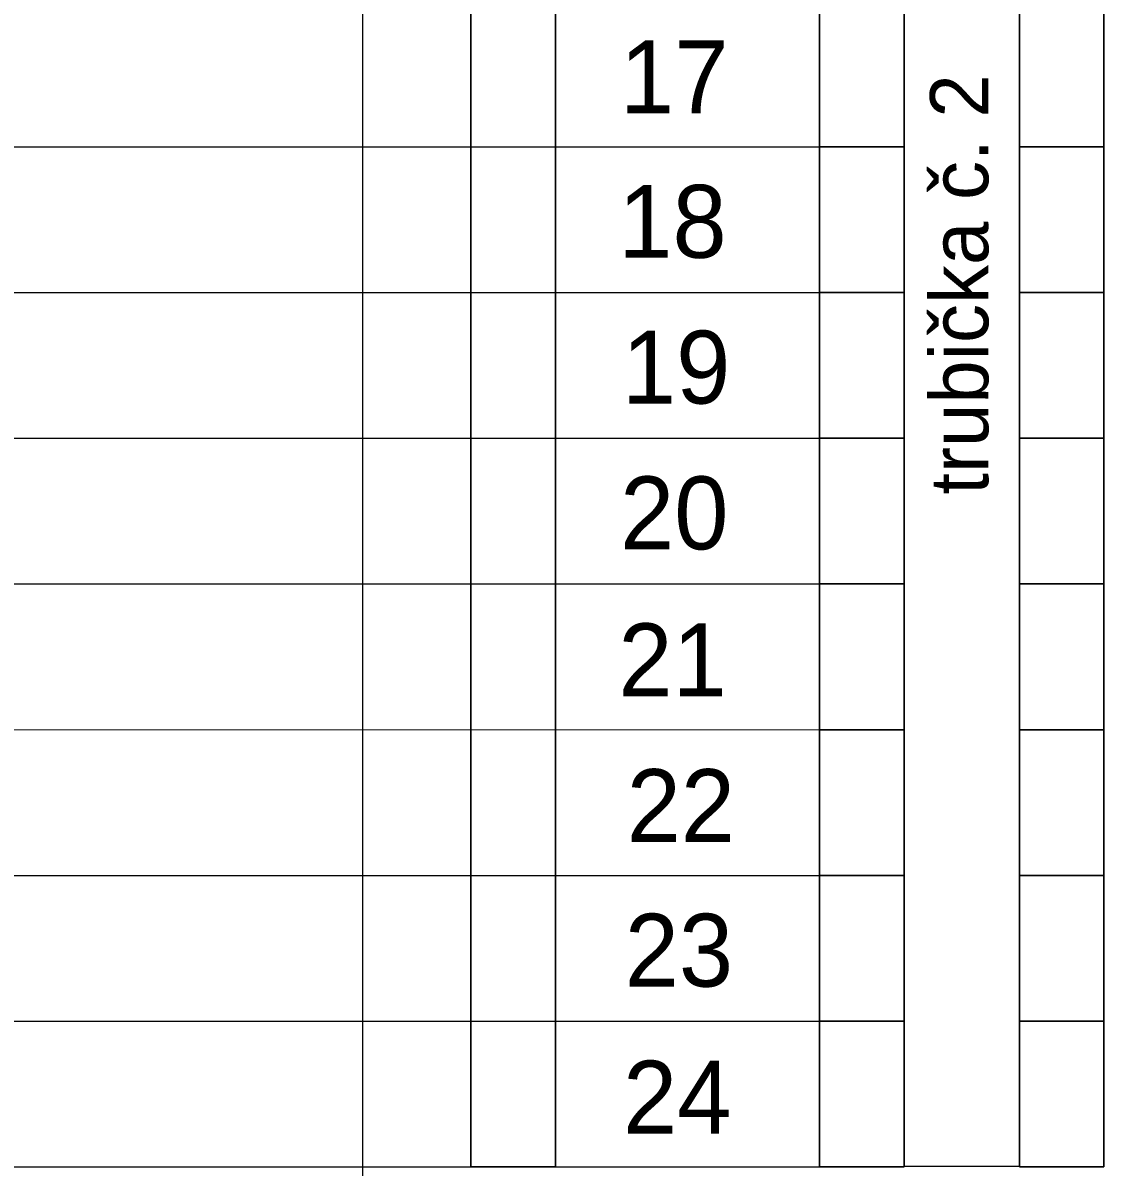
# Model space of a CAD drawing. Extents: x 1901 to 2519, y -3585 to -3154.
# Drawn here: x 2006.66 to 2032.79, y -3287.48 to -3259.84 of the extents above; entities that cross this region are included whole.
import ezdxf

# ---------------------------------------------------------------- set-up
doc = ezdxf.new("R2010")
doc.units = 0
doc.layers.add('rozvláknění', color=7, linetype='Continuous')

msp = doc.modelspace()

# ---------------------------------------------------------------- linework, layer by layer
at = {"layer": 'rozvláknění'}
for p, q in [((1933.193, -3262.837), (2025.898, -3262.839)), ((1933.193, -3266.355), (2025.898, -3266.357)), ((1933.193, -3269.874), (2025.898, -3269.876)), ((1933.193, -3273.392), (2025.898, -3273.394)), ((1933.193, -3276.91), (2025.898, -3276.912)), ((1933.193, -3280.428), (2025.898, -3280.43)), ((1933.193, -3283.946), (2025.898, -3283.948)), ((1933.193, -3287.465), (2025.898, -3287.467))]:
    msp.add_line(p, q, dxfattribs=at)
for points in [[(2014.869, -3178.545), (2059.522, -3178.544), (2059.522, -3570.656), (2014.869, -3570.656)], [(2019.518, -3287.467), (2017.476, -3287.467), (2017.476, -3245.248), (2019.518, -3245.248)], [(2027.939, -3245.248), (2030.726, -3245.248), (2030.726, -3287.463), (2027.939, -3287.463)], [(2025.898, -3259.321), (2027.939, -3259.321), (2027.939, -3262.839), (2025.898, -3262.839)], [(2030.726, -3259.321), (2032.767, -3259.321), (2032.767, -3262.839), (2030.726, -3262.839)], [(2030.726, -3259.321), (2032.767, -3259.321), (2032.767, -3262.839), (2030.726, -3262.839)], [(2025.898, -3262.839), (2027.939, -3262.839), (2027.939, -3266.357), (2025.898, -3266.357)], [(2030.726, -3262.839), (2032.767, -3262.839), (2032.767, -3266.357), (2030.726, -3266.357)], [(2030.726, -3262.839), (2032.767, -3262.839), (2032.767, -3266.357), (2030.726, -3266.357)], [(2025.898, -3266.357), (2027.939, -3266.357), (2027.939, -3269.876), (2025.898, -3269.876)], [(2030.726, -3266.357), (2032.767, -3266.357), (2032.767, -3269.876), (2030.726, -3269.876)], [(2030.726, -3266.357), (2032.767, -3266.357), (2032.767, -3269.876), (2030.726, -3269.876)], [(2025.898, -3269.876), (2027.939, -3269.876), (2027.939, -3273.394), (2025.898, -3273.394)], [(2030.726, -3269.876), (2032.767, -3269.876), (2032.767, -3273.394), (2030.726, -3273.394)], [(2030.726, -3269.876), (2032.767, -3269.876), (2032.767, -3273.394), (2030.726, -3273.394)], [(2025.898, -3273.394), (2027.939, -3273.394), (2027.939, -3276.912), (2025.898, -3276.912)], [(2030.726, -3273.394), (2032.767, -3273.394), (2032.767, -3276.912), (2030.726, -3276.912)], [(2030.726, -3273.394), (2032.767, -3273.394), (2032.767, -3276.912), (2030.726, -3276.912)], [(2025.898, -3276.912), (2027.939, -3276.912), (2027.939, -3280.43), (2025.898, -3280.43)], [(2030.726, -3276.912), (2032.767, -3276.912), (2032.767, -3280.43), (2030.726, -3280.43)], [(2030.726, -3276.912), (2032.767, -3276.912), (2032.767, -3280.43), (2030.726, -3280.43)], [(2025.898, -3280.43), (2027.939, -3280.43), (2027.939, -3283.948), (2025.898, -3283.948)], [(2030.726, -3280.43), (2032.767, -3280.43), (2032.767, -3283.948), (2030.726, -3283.948)], [(2030.726, -3280.43), (2032.767, -3280.43), (2032.767, -3283.948), (2030.726, -3283.948)], [(2025.898, -3283.948), (2027.939, -3283.948), (2027.939, -3287.467), (2025.898, -3287.467)], [(2030.726, -3283.948), (2032.767, -3283.948), (2032.767, -3287.467), (2030.726, -3287.467)], [(2030.726, -3283.948), (2032.767, -3283.948), (2032.767, -3287.467), (2030.726, -3287.467)]]:
    msp.add_lwpolyline(points, close=True, dxfattribs=at)
for points in [[(2019.518, -3245.248), (2017.476, -3245.248), (2017.476, -3287.467), (2019.518, -3287.467), (2019.518, -3245.248)], [(2019.518, -3245.248), (2017.476, -3245.248), (2017.476, -3287.467), (2019.518, -3287.467), (2019.518, -3245.248)], [(2019.518, -3245.248), (2017.476, -3245.248), (2017.476, -3287.467), (2019.518, -3287.467), (2019.518, -3245.248)], [(2019.518, -3245.248), (2017.476, -3245.248), (2017.476, -3287.467), (2019.518, -3287.467), (2019.518, -3245.248)], [(2019.518, -3245.248), (2017.476, -3245.248), (2017.476, -3287.467), (2019.518, -3287.467), (2019.518, -3245.248)], [(2019.518, -3245.248), (2017.476, -3245.248), (2017.476, -3287.467), (2019.518, -3287.467), (2019.518, -3245.248)], [(2025.898, -3262.839), (2027.939, -3262.839), (2027.939, -3259.321), (2025.898, -3259.321), (2025.898, -3262.839)], [(2025.898, -3262.839), (2027.939, -3262.839), (2027.939, -3259.321), (2025.898, -3259.321), (2025.898, -3262.839)], [(2025.898, -3262.839), (2027.939, -3262.839), (2027.939, -3259.321), (2025.898, -3259.321), (2025.898, -3262.839)], [(2025.898, -3262.839), (2027.939, -3262.839), (2027.939, -3259.321), (2025.898, -3259.321), (2025.898, -3262.839)], [(2025.898, -3262.839), (2027.939, -3262.839), (2027.939, -3259.321), (2025.898, -3259.321), (2025.898, -3262.839)], [(2025.898, -3262.839), (2027.939, -3262.839), (2027.939, -3259.321), (2025.898, -3259.321), (2025.898, -3262.839)], [(2025.898, -3262.839), (2027.939, -3262.839), (2027.939, -3259.321), (2025.898, -3259.321), (2025.898, -3262.839)], [(2025.898, -3262.839), (2027.939, -3262.839), (2027.939, -3259.321), (2025.898, -3259.321), (2025.898, -3262.839)], [(2025.898, -3262.839), (2027.939, -3262.839), (2027.939, -3259.321), (2025.898, -3259.321), (2025.898, -3262.839)], [(2025.898, -3262.839), (2027.939, -3262.839), (2027.939, -3259.321), (2025.898, -3259.321), (2025.898, -3262.839)], [(2030.726, -3262.839), (2032.767, -3262.839), (2032.767, -3259.321), (2030.726, -3259.321), (2030.726, -3262.839)], [(2030.726, -3262.839), (2032.767, -3262.839), (2032.767, -3259.321), (2030.726, -3259.321), (2030.726, -3262.839)], [(2030.726, -3262.839), (2032.767, -3262.839), (2032.767, -3259.321), (2030.726, -3259.321), (2030.726, -3262.839)], [(2030.726, -3262.839), (2032.767, -3262.839), (2032.767, -3259.321), (2030.726, -3259.321), (2030.726, -3262.839)], [(2030.726, -3262.839), (2032.767, -3262.839), (2032.767, -3259.321), (2030.726, -3259.321), (2030.726, -3262.839)], [(2030.726, -3262.839), (2032.767, -3262.839), (2032.767, -3259.321), (2030.726, -3259.321), (2030.726, -3262.839)], [(2030.726, -3262.839), (2032.767, -3262.839), (2032.767, -3259.321), (2030.726, -3259.321), (2030.726, -3262.839)], [(2030.726, -3262.839), (2032.767, -3262.839), (2032.767, -3259.321), (2030.726, -3259.321), (2030.726, -3262.839)], [(2030.726, -3262.839), (2032.767, -3262.839), (2032.767, -3259.321), (2030.726, -3259.321), (2030.726, -3262.839)], [(2030.726, -3262.839), (2032.767, -3262.839), (2032.767, -3259.321), (2030.726, -3259.321), (2030.726, -3262.839)], [(2025.898, -3266.357), (2027.939, -3266.357), (2027.939, -3262.839), (2025.898, -3262.839), (2025.898, -3266.357)], [(2025.898, -3266.357), (2027.939, -3266.357), (2027.939, -3262.839), (2025.898, -3262.839), (2025.898, -3266.357)], [(2025.898, -3266.357), (2027.939, -3266.357), (2027.939, -3262.839), (2025.898, -3262.839), (2025.898, -3266.357)], [(2025.898, -3266.357), (2027.939, -3266.357), (2027.939, -3262.839), (2025.898, -3262.839), (2025.898, -3266.357)], [(2025.898, -3266.357), (2027.939, -3266.357), (2027.939, -3262.839), (2025.898, -3262.839), (2025.898, -3266.357)], [(2025.898, -3266.357), (2027.939, -3266.357), (2027.939, -3262.839), (2025.898, -3262.839), (2025.898, -3266.357)], [(2025.898, -3266.357), (2027.939, -3266.357), (2027.939, -3262.839), (2025.898, -3262.839), (2025.898, -3266.357)], [(2025.898, -3266.357), (2027.939, -3266.357), (2027.939, -3262.839), (2025.898, -3262.839), (2025.898, -3266.357)], [(2025.898, -3266.357), (2027.939, -3266.357), (2027.939, -3262.839), (2025.898, -3262.839), (2025.898, -3266.357)], [(2025.898, -3266.357), (2027.939, -3266.357), (2027.939, -3262.839), (2025.898, -3262.839), (2025.898, -3266.357)], [(2030.726, -3266.357), (2032.767, -3266.357), (2032.767, -3262.839), (2030.726, -3262.839), (2030.726, -3266.357)], [(2030.726, -3266.357), (2032.767, -3266.357), (2032.767, -3262.839), (2030.726, -3262.839), (2030.726, -3266.357)], [(2030.726, -3266.357), (2032.767, -3266.357), (2032.767, -3262.839), (2030.726, -3262.839), (2030.726, -3266.357)], [(2030.726, -3266.357), (2032.767, -3266.357), (2032.767, -3262.839), (2030.726, -3262.839), (2030.726, -3266.357)], [(2030.726, -3266.357), (2032.767, -3266.357), (2032.767, -3262.839), (2030.726, -3262.839), (2030.726, -3266.357)], [(2030.726, -3266.357), (2032.767, -3266.357), (2032.767, -3262.839), (2030.726, -3262.839), (2030.726, -3266.357)], [(2030.726, -3266.357), (2032.767, -3266.357), (2032.767, -3262.839), (2030.726, -3262.839), (2030.726, -3266.357)], [(2030.726, -3266.357), (2032.767, -3266.357), (2032.767, -3262.839), (2030.726, -3262.839), (2030.726, -3266.357)], [(2030.726, -3266.357), (2032.767, -3266.357), (2032.767, -3262.839), (2030.726, -3262.839), (2030.726, -3266.357)], [(2030.726, -3266.357), (2032.767, -3266.357), (2032.767, -3262.839), (2030.726, -3262.839), (2030.726, -3266.357)], [(2025.898, -3269.876), (2027.939, -3269.876), (2027.939, -3266.357), (2025.898, -3266.357), (2025.898, -3269.876)], [(2025.898, -3269.876), (2027.939, -3269.876), (2027.939, -3266.357), (2025.898, -3266.357), (2025.898, -3269.876)], [(2025.898, -3269.876), (2027.939, -3269.876), (2027.939, -3266.357), (2025.898, -3266.357), (2025.898, -3269.876)], [(2025.898, -3269.876), (2027.939, -3269.876), (2027.939, -3266.357), (2025.898, -3266.357), (2025.898, -3269.876)], [(2025.898, -3269.876), (2027.939, -3269.876), (2027.939, -3266.357), (2025.898, -3266.357), (2025.898, -3269.876)], [(2025.898, -3269.876), (2027.939, -3269.876), (2027.939, -3266.357), (2025.898, -3266.357), (2025.898, -3269.876)], [(2025.898, -3269.876), (2027.939, -3269.876), (2027.939, -3266.357), (2025.898, -3266.357), (2025.898, -3269.876)], [(2025.898, -3269.876), (2027.939, -3269.876), (2027.939, -3266.357), (2025.898, -3266.357), (2025.898, -3269.876)], [(2025.898, -3269.876), (2027.939, -3269.876), (2027.939, -3266.357), (2025.898, -3266.357), (2025.898, -3269.876)], [(2025.898, -3269.876), (2027.939, -3269.876), (2027.939, -3266.357), (2025.898, -3266.357), (2025.898, -3269.876)], [(2030.726, -3269.876), (2032.767, -3269.876), (2032.767, -3266.357), (2030.726, -3266.357), (2030.726, -3269.876)], [(2030.726, -3269.876), (2032.767, -3269.876), (2032.767, -3266.357), (2030.726, -3266.357), (2030.726, -3269.876)], [(2030.726, -3269.876), (2032.767, -3269.876), (2032.767, -3266.357), (2030.726, -3266.357), (2030.726, -3269.876)], [(2030.726, -3269.876), (2032.767, -3269.876), (2032.767, -3266.357), (2030.726, -3266.357), (2030.726, -3269.876)], [(2030.726, -3269.876), (2032.767, -3269.876), (2032.767, -3266.357), (2030.726, -3266.357), (2030.726, -3269.876)], [(2030.726, -3269.876), (2032.767, -3269.876), (2032.767, -3266.357), (2030.726, -3266.357), (2030.726, -3269.876)], [(2030.726, -3269.876), (2032.767, -3269.876), (2032.767, -3266.357), (2030.726, -3266.357), (2030.726, -3269.876)], [(2030.726, -3269.876), (2032.767, -3269.876), (2032.767, -3266.357), (2030.726, -3266.357), (2030.726, -3269.876)], [(2030.726, -3269.876), (2032.767, -3269.876), (2032.767, -3266.357), (2030.726, -3266.357), (2030.726, -3269.876)], [(2030.726, -3269.876), (2032.767, -3269.876), (2032.767, -3266.357), (2030.726, -3266.357), (2030.726, -3269.876)], [(2025.898, -3273.394), (2027.939, -3273.394), (2027.939, -3269.876), (2025.898, -3269.876), (2025.898, -3273.394)], [(2025.898, -3273.394), (2027.939, -3273.394), (2027.939, -3269.876), (2025.898, -3269.876), (2025.898, -3273.394)], [(2025.898, -3273.394), (2027.939, -3273.394), (2027.939, -3269.876), (2025.898, -3269.876), (2025.898, -3273.394)], [(2025.898, -3273.394), (2027.939, -3273.394), (2027.939, -3269.876), (2025.898, -3269.876), (2025.898, -3273.394)], [(2025.898, -3273.394), (2027.939, -3273.394), (2027.939, -3269.876), (2025.898, -3269.876), (2025.898, -3273.394)], [(2025.898, -3273.394), (2027.939, -3273.394), (2027.939, -3269.876), (2025.898, -3269.876), (2025.898, -3273.394)], [(2025.898, -3273.394), (2027.939, -3273.394), (2027.939, -3269.876), (2025.898, -3269.876), (2025.898, -3273.394)], [(2025.898, -3273.394), (2027.939, -3273.394), (2027.939, -3269.876), (2025.898, -3269.876), (2025.898, -3273.394)], [(2025.898, -3273.394), (2027.939, -3273.394), (2027.939, -3269.876), (2025.898, -3269.876), (2025.898, -3273.394)], [(2025.898, -3273.394), (2027.939, -3273.394), (2027.939, -3269.876), (2025.898, -3269.876), (2025.898, -3273.394)], [(2030.726, -3273.394), (2032.767, -3273.394), (2032.767, -3269.876), (2030.726, -3269.876), (2030.726, -3273.394)], [(2030.726, -3273.394), (2032.767, -3273.394), (2032.767, -3269.876), (2030.726, -3269.876), (2030.726, -3273.394)], [(2030.726, -3273.394), (2032.767, -3273.394), (2032.767, -3269.876), (2030.726, -3269.876), (2030.726, -3273.394)], [(2030.726, -3273.394), (2032.767, -3273.394), (2032.767, -3269.876), (2030.726, -3269.876), (2030.726, -3273.394)], [(2030.726, -3273.394), (2032.767, -3273.394), (2032.767, -3269.876), (2030.726, -3269.876), (2030.726, -3273.394)], [(2030.726, -3273.394), (2032.767, -3273.394), (2032.767, -3269.876), (2030.726, -3269.876), (2030.726, -3273.394)], [(2030.726, -3273.394), (2032.767, -3273.394), (2032.767, -3269.876), (2030.726, -3269.876), (2030.726, -3273.394)], [(2030.726, -3273.394), (2032.767, -3273.394), (2032.767, -3269.876), (2030.726, -3269.876), (2030.726, -3273.394)], [(2030.726, -3273.394), (2032.767, -3273.394), (2032.767, -3269.876), (2030.726, -3269.876), (2030.726, -3273.394)], [(2030.726, -3273.394), (2032.767, -3273.394), (2032.767, -3269.876), (2030.726, -3269.876), (2030.726, -3273.394)], [(2025.898, -3276.912), (2027.939, -3276.912), (2027.939, -3273.394), (2025.898, -3273.394), (2025.898, -3276.912)], [(2025.898, -3276.912), (2027.939, -3276.912), (2027.939, -3273.394), (2025.898, -3273.394), (2025.898, -3276.912)], [(2025.898, -3276.912), (2027.939, -3276.912), (2027.939, -3273.394), (2025.898, -3273.394), (2025.898, -3276.912)], [(2025.898, -3276.912), (2027.939, -3276.912), (2027.939, -3273.394), (2025.898, -3273.394), (2025.898, -3276.912)], [(2025.898, -3276.912), (2027.939, -3276.912), (2027.939, -3273.394), (2025.898, -3273.394), (2025.898, -3276.912)], [(2025.898, -3276.912), (2027.939, -3276.912), (2027.939, -3273.394), (2025.898, -3273.394), (2025.898, -3276.912)], [(2025.898, -3276.912), (2027.939, -3276.912), (2027.939, -3273.394), (2025.898, -3273.394), (2025.898, -3276.912)], [(2025.898, -3276.912), (2027.939, -3276.912), (2027.939, -3273.394), (2025.898, -3273.394), (2025.898, -3276.912)], [(2025.898, -3276.912), (2027.939, -3276.912), (2027.939, -3273.394), (2025.898, -3273.394), (2025.898, -3276.912)], [(2025.898, -3276.912), (2027.939, -3276.912), (2027.939, -3273.394), (2025.898, -3273.394), (2025.898, -3276.912)], [(2030.726, -3276.912), (2032.767, -3276.912), (2032.767, -3273.394), (2030.726, -3273.394), (2030.726, -3276.912)], [(2030.726, -3276.912), (2032.767, -3276.912), (2032.767, -3273.394), (2030.726, -3273.394), (2030.726, -3276.912)], [(2030.726, -3276.912), (2032.767, -3276.912), (2032.767, -3273.394), (2030.726, -3273.394), (2030.726, -3276.912)], [(2030.726, -3276.912), (2032.767, -3276.912), (2032.767, -3273.394), (2030.726, -3273.394), (2030.726, -3276.912)], [(2030.726, -3276.912), (2032.767, -3276.912), (2032.767, -3273.394), (2030.726, -3273.394), (2030.726, -3276.912)], [(2030.726, -3276.912), (2032.767, -3276.912), (2032.767, -3273.394), (2030.726, -3273.394), (2030.726, -3276.912)], [(2030.726, -3276.912), (2032.767, -3276.912), (2032.767, -3273.394), (2030.726, -3273.394), (2030.726, -3276.912)], [(2030.726, -3276.912), (2032.767, -3276.912), (2032.767, -3273.394), (2030.726, -3273.394), (2030.726, -3276.912)], [(2030.726, -3276.912), (2032.767, -3276.912), (2032.767, -3273.394), (2030.726, -3273.394), (2030.726, -3276.912)], [(2030.726, -3276.912), (2032.767, -3276.912), (2032.767, -3273.394), (2030.726, -3273.394), (2030.726, -3276.912)], [(2025.898, -3280.43), (2027.939, -3280.43), (2027.939, -3276.912), (2025.898, -3276.912), (2025.898, -3280.43)], [(2025.898, -3280.43), (2027.939, -3280.43), (2027.939, -3276.912), (2025.898, -3276.912), (2025.898, -3280.43)], [(2025.898, -3280.43), (2027.939, -3280.43), (2027.939, -3276.912), (2025.898, -3276.912), (2025.898, -3280.43)], [(2025.898, -3280.43), (2027.939, -3280.43), (2027.939, -3276.912), (2025.898, -3276.912), (2025.898, -3280.43)], [(2025.898, -3280.43), (2027.939, -3280.43), (2027.939, -3276.912), (2025.898, -3276.912), (2025.898, -3280.43)], [(2025.898, -3280.43), (2027.939, -3280.43), (2027.939, -3276.912), (2025.898, -3276.912), (2025.898, -3280.43)], [(2025.898, -3280.43), (2027.939, -3280.43), (2027.939, -3276.912), (2025.898, -3276.912), (2025.898, -3280.43)], [(2025.898, -3280.43), (2027.939, -3280.43), (2027.939, -3276.912), (2025.898, -3276.912), (2025.898, -3280.43)], [(2025.898, -3280.43), (2027.939, -3280.43), (2027.939, -3276.912), (2025.898, -3276.912), (2025.898, -3280.43)], [(2025.898, -3280.43), (2027.939, -3280.43), (2027.939, -3276.912), (2025.898, -3276.912), (2025.898, -3280.43)], [(2030.726, -3280.43), (2032.767, -3280.43), (2032.767, -3276.912), (2030.726, -3276.912), (2030.726, -3280.43)], [(2030.726, -3280.43), (2032.767, -3280.43), (2032.767, -3276.912), (2030.726, -3276.912), (2030.726, -3280.43)], [(2030.726, -3280.43), (2032.767, -3280.43), (2032.767, -3276.912), (2030.726, -3276.912), (2030.726, -3280.43)], [(2030.726, -3280.43), (2032.767, -3280.43), (2032.767, -3276.912), (2030.726, -3276.912), (2030.726, -3280.43)], [(2030.726, -3280.43), (2032.767, -3280.43), (2032.767, -3276.912), (2030.726, -3276.912), (2030.726, -3280.43)], [(2030.726, -3280.43), (2032.767, -3280.43), (2032.767, -3276.912), (2030.726, -3276.912), (2030.726, -3280.43)], [(2030.726, -3280.43), (2032.767, -3280.43), (2032.767, -3276.912), (2030.726, -3276.912), (2030.726, -3280.43)], [(2030.726, -3280.43), (2032.767, -3280.43), (2032.767, -3276.912), (2030.726, -3276.912), (2030.726, -3280.43)], [(2030.726, -3280.43), (2032.767, -3280.43), (2032.767, -3276.912), (2030.726, -3276.912), (2030.726, -3280.43)], [(2030.726, -3280.43), (2032.767, -3280.43), (2032.767, -3276.912), (2030.726, -3276.912), (2030.726, -3280.43)], [(2025.898, -3283.948), (2027.939, -3283.948), (2027.939, -3280.43), (2025.898, -3280.43), (2025.898, -3283.948)], [(2025.898, -3283.948), (2027.939, -3283.948), (2027.939, -3280.43), (2025.898, -3280.43), (2025.898, -3283.948)], [(2025.898, -3283.948), (2027.939, -3283.948), (2027.939, -3280.43), (2025.898, -3280.43), (2025.898, -3283.948)], [(2025.898, -3283.948), (2027.939, -3283.948), (2027.939, -3280.43), (2025.898, -3280.43), (2025.898, -3283.948)], [(2025.898, -3283.948), (2027.939, -3283.948), (2027.939, -3280.43), (2025.898, -3280.43), (2025.898, -3283.948)], [(2025.898, -3283.948), (2027.939, -3283.948), (2027.939, -3280.43), (2025.898, -3280.43), (2025.898, -3283.948)], [(2025.898, -3283.948), (2027.939, -3283.948), (2027.939, -3280.43), (2025.898, -3280.43), (2025.898, -3283.948)], [(2025.898, -3283.948), (2027.939, -3283.948), (2027.939, -3280.43), (2025.898, -3280.43), (2025.898, -3283.948)], [(2025.898, -3283.948), (2027.939, -3283.948), (2027.939, -3280.43), (2025.898, -3280.43), (2025.898, -3283.948)], [(2025.898, -3283.948), (2027.939, -3283.948), (2027.939, -3280.43), (2025.898, -3280.43), (2025.898, -3283.948)], [(2030.726, -3283.948), (2032.767, -3283.948), (2032.767, -3280.43), (2030.726, -3280.43), (2030.726, -3283.948)], [(2030.726, -3283.948), (2032.767, -3283.948), (2032.767, -3280.43), (2030.726, -3280.43), (2030.726, -3283.948)], [(2030.726, -3283.948), (2032.767, -3283.948), (2032.767, -3280.43), (2030.726, -3280.43), (2030.726, -3283.948)], [(2030.726, -3283.948), (2032.767, -3283.948), (2032.767, -3280.43), (2030.726, -3280.43), (2030.726, -3283.948)], [(2030.726, -3283.948), (2032.767, -3283.948), (2032.767, -3280.43), (2030.726, -3280.43), (2030.726, -3283.948)], [(2030.726, -3283.948), (2032.767, -3283.948), (2032.767, -3280.43), (2030.726, -3280.43), (2030.726, -3283.948)], [(2030.726, -3283.948), (2032.767, -3283.948), (2032.767, -3280.43), (2030.726, -3280.43), (2030.726, -3283.948)], [(2030.726, -3283.948), (2032.767, -3283.948), (2032.767, -3280.43), (2030.726, -3280.43), (2030.726, -3283.948)], [(2030.726, -3283.948), (2032.767, -3283.948), (2032.767, -3280.43), (2030.726, -3280.43), (2030.726, -3283.948)], [(2030.726, -3283.948), (2032.767, -3283.948), (2032.767, -3280.43), (2030.726, -3280.43), (2030.726, -3283.948)], [(2025.898, -3287.467), (2027.939, -3287.467), (2027.939, -3283.948), (2025.898, -3283.948), (2025.898, -3287.467)], [(2025.898, -3287.467), (2027.939, -3287.467), (2027.939, -3283.948), (2025.898, -3283.948), (2025.898, -3287.467)], [(2025.898, -3287.467), (2027.939, -3287.467), (2027.939, -3283.948), (2025.898, -3283.948), (2025.898, -3287.467)], [(2025.898, -3287.467), (2027.939, -3287.467), (2027.939, -3283.948), (2025.898, -3283.948), (2025.898, -3287.467)], [(2025.898, -3287.467), (2027.939, -3287.467), (2027.939, -3283.948), (2025.898, -3283.948), (2025.898, -3287.467)], [(2025.898, -3287.467), (2027.939, -3287.467), (2027.939, -3283.948), (2025.898, -3283.948), (2025.898, -3287.467)], [(2025.898, -3287.467), (2027.939, -3287.467), (2027.939, -3283.948), (2025.898, -3283.948), (2025.898, -3287.467)], [(2025.898, -3287.467), (2027.939, -3287.467), (2027.939, -3283.948), (2025.898, -3283.948), (2025.898, -3287.467)], [(2025.898, -3287.467), (2027.939, -3287.467), (2027.939, -3283.948), (2025.898, -3283.948), (2025.898, -3287.467)], [(2025.898, -3287.467), (2027.939, -3287.467), (2027.939, -3283.948), (2025.898, -3283.948), (2025.898, -3287.467)], [(2030.726, -3287.467), (2032.767, -3287.467), (2032.767, -3283.948), (2030.726, -3283.948), (2030.726, -3287.467)], [(2030.726, -3287.467), (2032.767, -3287.467), (2032.767, -3283.948), (2030.726, -3283.948), (2030.726, -3287.467)], [(2030.726, -3287.467), (2032.767, -3287.467), (2032.767, -3283.948), (2030.726, -3283.948), (2030.726, -3287.467)], [(2030.726, -3287.467), (2032.767, -3287.467), (2032.767, -3283.948), (2030.726, -3283.948), (2030.726, -3287.467)], [(2030.726, -3287.467), (2032.767, -3287.467), (2032.767, -3283.948), (2030.726, -3283.948), (2030.726, -3287.467)], [(2030.726, -3287.467), (2032.767, -3287.467), (2032.767, -3283.948), (2030.726, -3283.948), (2030.726, -3287.467)], [(2030.726, -3287.467), (2032.767, -3287.467), (2032.767, -3283.948), (2030.726, -3283.948), (2030.726, -3287.467)], [(2030.726, -3287.467), (2032.767, -3287.467), (2032.767, -3283.948), (2030.726, -3283.948), (2030.726, -3287.467)], [(2030.726, -3287.467), (2032.767, -3287.467), (2032.767, -3283.948), (2030.726, -3283.948), (2030.726, -3287.467)], [(2030.726, -3287.467), (2032.767, -3287.467), (2032.767, -3283.948), (2030.726, -3283.948), (2030.726, -3287.467)]]:
    msp.add_lwpolyline(points, dxfattribs=at)

# ---------------------------------------------------------------- texts
for s, p in [('17', (2021.079, -3262.026)), ('18', (2021.037, -3265.517)), ('19', (2021.125, -3269.037)), ('20', (2021.079, -3272.557)), ('21', (2021.037, -3276.106)), ('22', (2021.239, -3279.626)), ('23', (2021.192, -3283.117)), ('24', (2021.15, -3286.666))]:
    msp.add_text(s, height=1.76, dxfattribs=at).set_placement(p)
msp.add_text('trubička č. 2', height=1.408, rotation=90, dxfattribs=at).set_placement((2029.974, -3271.237))

doc.saveas('drawing.dxf')
